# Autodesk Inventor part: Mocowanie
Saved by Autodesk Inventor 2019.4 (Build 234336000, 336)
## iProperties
Created: 2020-01
Part Number: Mocowanie
Material: Generic
Document SubType Name: Modeling
Designer: Administrator
Density: 1 g/cm^3
Appearance: Default
Title: Mocowanie v6
Author: Administrator
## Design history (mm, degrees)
feature "Body3"
body "Solid1"
